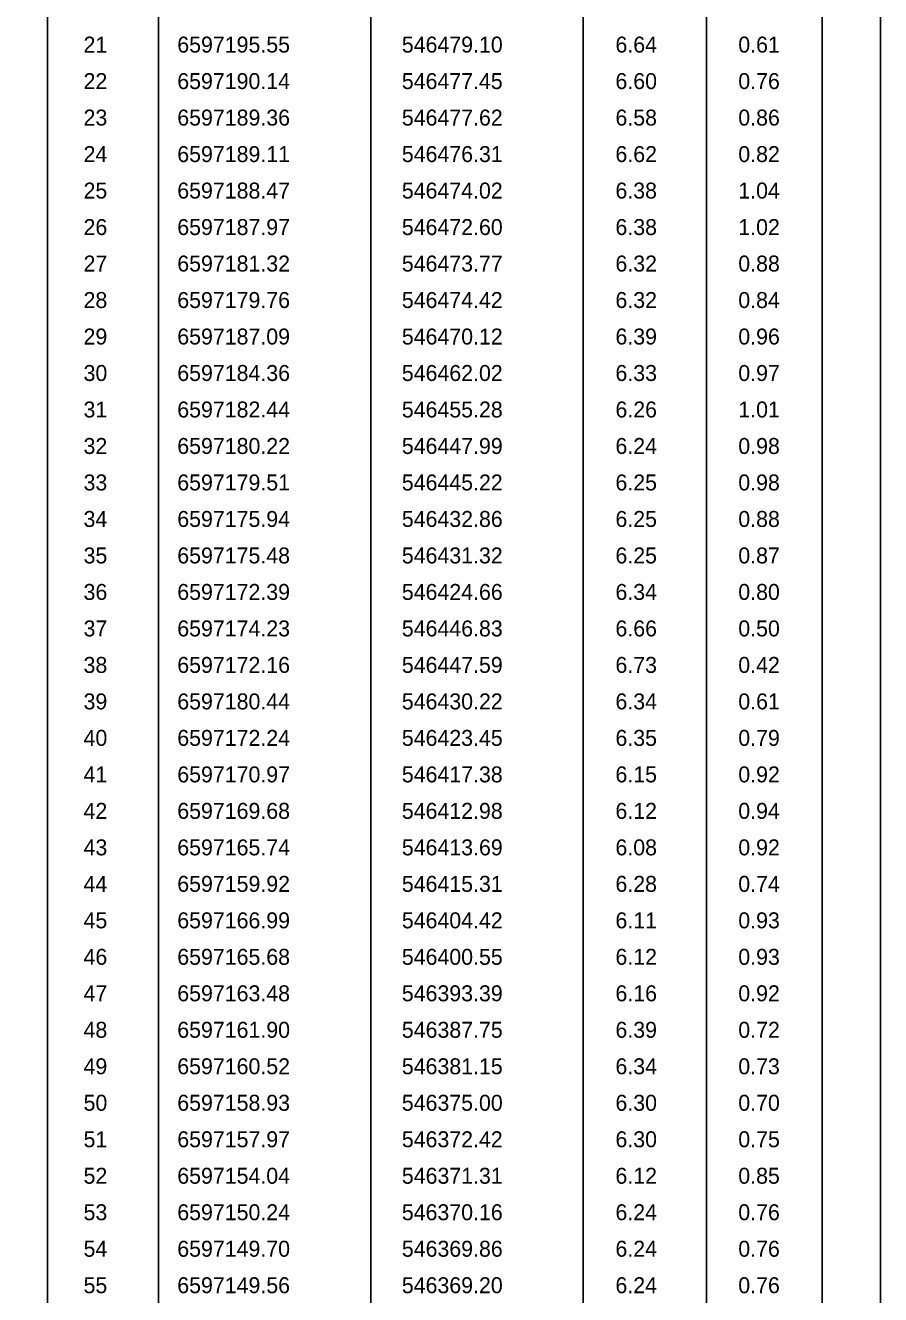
# Model space of a CAD drawing. Extents: x 546339 to 546593, y 6597108 to 6597251.
# Drawn here: x 546555.7 to 546593.2, y 6597155.9 to 6597211.5 of the extents above; entities that cross this region are included whole.
import ezdxf

# ---------------------------------------------------------------- set-up
doc = ezdxf.new("R2010")
doc.units = 0
doc.layers.add('ABIJOONIS', color=7, linetype='Continuous')
doc.layers.add('VORMISTUS', color=7, linetype='Continuous')

msp = doc.modelspace()

# ---------------------------------------------------------------- linework, layer by layer
at = {"layer": 'ABIJOONIS'}
for p, q in [((546556.632, 6597245.851), (546556.632, 6597153.547)), ((546561.492, 6597245.851), (546561.492, 6597153.547)), ((546570.807, 6597245.851), (546570.807, 6597153.547)), ((546580.122, 6597245.851), (546580.122, 6597153.547)), ((546585.544, 6597245.851), (546585.544, 6597153.547)), ((546590.616, 6597245.851), (546590.616, 6597153.547))]:
    msp.add_line(p, q, dxfattribs=at)
at = {"layer": 'VORMISTUS'}
msp.add_lwpolyline([(546593.177, 6597250.72), (546339.379, 6597250.72), (546339.379, 6597108.37), (546593.177, 6597108.37)], close=True, dxfattribs=at)

# ---------------------------------------------------------------- texts
at = {"layer": 'ABIJOONIS'}
for s, p in [('21', (546558.211, 6597210.332)), ('6597195.55', (546562.323, 6597210.332)), ('546479.10', (546572.174, 6597210.332)), ('6.64', (546581.545, 6597210.332)), ('0.61', (546586.934, 6597210.332)), ('22', (546558.211, 6597208.732)), ('6597190.14', (546562.323, 6597208.732)), ('546477.45', (546572.174, 6597208.732)), ('6.60', (546581.545, 6597208.732)), ('0.76', (546586.934, 6597208.732)), ('23', (546558.211, 6597207.132)), ('6597189.36', (546562.323, 6597207.132)), ('546477.62', (546572.174, 6597207.132)), ('6.58', (546581.545, 6597207.132)), ('0.86', (546586.934, 6597207.132)), ('24', (546558.211, 6597205.532)), ('6597189.11', (546562.323, 6597205.532)), ('546476.31', (546572.174, 6597205.532)), ('6.62', (546581.545, 6597205.532)), ('0.82', (546586.934, 6597205.532)), ('25', (546558.211, 6597203.932)), ('6597188.47', (546562.323, 6597203.932)), ('546474.02', (546572.174, 6597203.932)), ('6.38', (546581.545, 6597203.932)), ('1.04', (546586.934, 6597203.932)), ('26', (546558.211, 6597202.332)), ('6597187.97', (546562.323, 6597202.332)), ('546472.60', (546572.174, 6597202.332)), ('6.38', (546581.545, 6597202.332)), ('1.02', (546586.934, 6597202.332)), ('27', (546558.211, 6597200.732)), ('6597181.32', (546562.323, 6597200.732)), ('546473.77', (546572.174, 6597200.732)), ('6.32', (546581.545, 6597200.732)), ('0.88', (546586.934, 6597200.732)), ('28', (546558.211, 6597199.132)), ('6597179.76', (546562.323, 6597199.132)), ('546474.42', (546572.174, 6597199.132)), ('6.32', (546581.545, 6597199.132)), ('0.84', (546586.934, 6597199.132)), ('29', (546558.211, 6597197.532)), ('6597187.09', (546562.323, 6597197.532)), ('546470.12', (546572.174, 6597197.532)), ('6.39', (546581.545, 6597197.532)), ('0.96', (546586.934, 6597197.532)), ('30', (546558.211, 6597195.932)), ('6597184.36', (546562.323, 6597195.932)), ('546462.02', (546572.174, 6597195.932)), ('6.33', (546581.545, 6597195.932)), ('0.97', (546586.934, 6597195.932)), ('31', (546558.211, 6597194.332)), ('6597182.44', (546562.323, 6597194.332)), ('546455.28', (546572.174, 6597194.332)), ('6.26', (546581.545, 6597194.332)), ('1.01', (546586.934, 6597194.332)), ('32', (546558.211, 6597192.732)), ('6597180.22', (546562.323, 6597192.732)), ('546447.99', (546572.174, 6597192.732)), ('6.24', (546581.545, 6597192.732)), ('0.98', (546586.934, 6597192.732)), ('33', (546558.211, 6597191.132)), ('6597179.51', (546562.323, 6597191.132)), ('546445.22', (546572.174, 6597191.132)), ('6.25', (546581.545, 6597191.132)), ('0.98', (546586.934, 6597191.132)), ('34', (546558.211, 6597189.532)), ('6597175.94', (546562.323, 6597189.532)), ('546432.86', (546572.174, 6597189.532)), ('6.25', (546581.545, 6597189.532)), ('0.88', (546586.934, 6597189.532)), ('35', (546558.211, 6597187.932)), ('6597175.48', (546562.323, 6597187.932)), ('546431.32', (546572.174, 6597187.932)), ('6.25', (546581.545, 6597187.932)), ('0.87', (546586.934, 6597187.932)), ('36', (546558.211, 6597186.332)), ('6597172.39', (546562.323, 6597186.332)), ('546424.66', (546572.174, 6597186.332)), ('6.34', (546581.545, 6597186.332)), ('0.80', (546586.934, 6597186.332)), ('37', (546558.211, 6597184.732)), ('6597174.23', (546562.323, 6597184.732)), ('546446.83', (546572.174, 6597184.732)), ('6.66', (546581.545, 6597184.732)), ('0.50', (546586.934, 6597184.732)), ('38', (546558.211, 6597183.132)), ('6597172.16', (546562.323, 6597183.132)), ('546447.59', (546572.174, 6597183.132)), ('6.73', (546581.545, 6597183.132)), ('0.42', (546586.934, 6597183.132)), ('39', (546558.211, 6597181.532)), ('6597180.44', (546562.323, 6597181.532)), ('546430.22', (546572.174, 6597181.532)), ('6.34', (546581.545, 6597181.532)), ('0.61', (546586.934, 6597181.532)), ('40', (546558.211, 6597179.932)), ('6597172.24', (546562.323, 6597179.932)), ('546423.45', (546572.174, 6597179.932)), ('6.35', (546581.545, 6597179.932)), ('0.79', (546586.934, 6597179.932)), ('41', (546558.211, 6597178.332)), ('6597170.97', (546562.323, 6597178.332)), ('546417.38', (546572.174, 6597178.332)), ('6.15', (546581.545, 6597178.332)), ('0.92', (546586.934, 6597178.332)), ('42', (546558.211, 6597176.732)), ('6597169.68', (546562.323, 6597176.732)), ('546412.98', (546572.174, 6597176.732)), ('6.12', (546581.545, 6597176.732)), ('0.94', (546586.934, 6597176.732)), ('43', (546558.211, 6597175.132)), ('6597165.74', (546562.323, 6597175.132)), ('546413.69', (546572.174, 6597175.132)), ('6.08', (546581.545, 6597175.132)), ('0.92', (546586.934, 6597175.132)), ('44', (546558.211, 6597173.532)), ('6597159.92', (546562.323, 6597173.532)), ('546415.31', (546572.174, 6597173.532)), ('6.28', (546581.545, 6597173.532)), ('0.74', (546586.934, 6597173.532)), ('45', (546558.211, 6597171.932)), ('6597166.99', (546562.323, 6597171.932)), ('546404.42', (546572.174, 6597171.932)), ('6.11', (546581.545, 6597171.932)), ('0.93', (546586.934, 6597171.932)), ('46', (546558.211, 6597170.332)), ('6597165.68', (546562.323, 6597170.332)), ('546400.55', (546572.174, 6597170.332)), ('6.12', (546581.545, 6597170.332)), ('0.93', (546586.934, 6597170.332)), ('47', (546558.211, 6597168.732)), ('6597163.48', (546562.323, 6597168.732)), ('546393.39', (546572.174, 6597168.732)), ('6.16', (546581.545, 6597168.732)), ('0.92', (546586.934, 6597168.732)), ('48', (546558.211, 6597167.132)), ('6597161.90', (546562.323, 6597167.132)), ('546387.75', (546572.174, 6597167.132)), ('6.39', (546581.545, 6597167.132)), ('0.72', (546586.934, 6597167.132)), ('49', (546558.211, 6597165.532)), ('6597160.52', (546562.323, 6597165.532)), ('546381.15', (546572.174, 6597165.532)), ('6.34', (546581.545, 6597165.532)), ('0.73', (546586.934, 6597165.532)), ('50', (546558.211, 6597163.932)), ('6597158.93', (546562.323, 6597163.932)), ('546375.00', (546572.174, 6597163.932)), ('6.30', (546581.545, 6597163.932)), ('0.70', (546586.934, 6597163.932)), ('51', (546558.211, 6597162.332)), ('6597157.97', (546562.323, 6597162.332)), ('546372.42', (546572.174, 6597162.332)), ('6.30', (546581.545, 6597162.332)), ('0.75', (546586.934, 6597162.332)), ('52', (546558.211, 6597160.732)), ('6597154.04', (546562.323, 6597160.732)), ('546371.31', (546572.174, 6597160.732)), ('6.12', (546581.545, 6597160.732)), ('0.85', (546586.934, 6597160.732)), ('53', (546558.211, 6597159.132)), ('6597150.24', (546562.323, 6597159.132)), ('546370.16', (546572.174, 6597159.132)), ('6.24', (546581.545, 6597159.132)), ('0.76', (546586.934, 6597159.132)), ('54', (546558.211, 6597157.532)), ('6597149.70', (546562.323, 6597157.532)), ('546369.86', (546572.174, 6597157.532)), ('6.24', (546581.545, 6597157.532)), ('0.76', (546586.934, 6597157.532)), ('55', (546558.211, 6597155.932)), ('6597149.56', (546562.323, 6597155.932)), ('546369.20', (546572.174, 6597155.932)), ('6.24', (546581.545, 6597155.932)), ('0.76', (546586.934, 6597155.932))]:
    msp.add_text(s, height=0.7, dxfattribs=at).set_placement(p)

doc.saveas('drawing.dxf')
